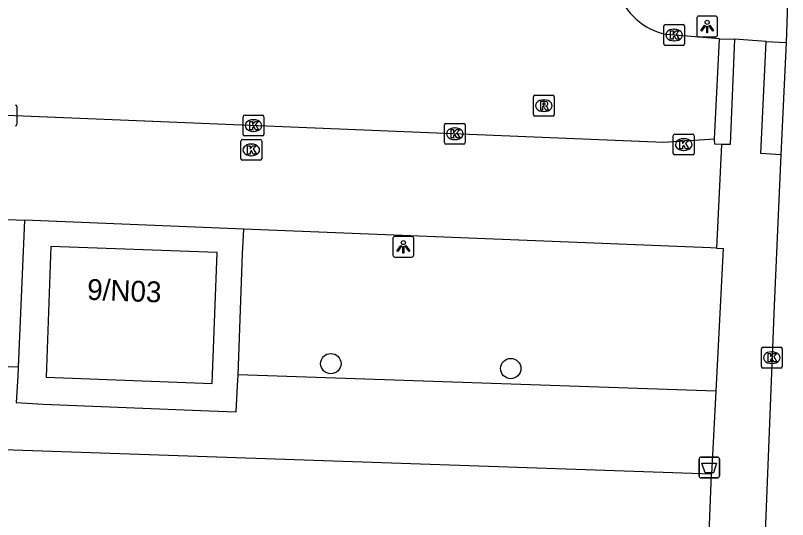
# Model space of a CAD drawing. Extents: x 160787 to 161428, y 386828 to 387483.
# Drawn here: x 160898.21 to 160935.33, y 387331.38 to 387355.63 of the extents above; entities that cross this region are included whole.
import ezdxf

# ---------------------------------------------------------------- set-up
doc = ezdxf.new("R2010")
doc.units = 0
for name, color, linetype in [('IMGEO_Afvalbak', 7, 'Continuous'), ('IMGEO_Boom', 7, 'Continuous'), ('IMGEO_Groenvoorziening', 7, 'Continuous'), ('IMGEO_Kolk', 7, 'Continuous'), ('IMGEO_Lichtpunt', 7, 'Continuous'), ('IMGEO_Pand', 7, 'Continuous'), ('IMGEO_Pand_nummerreeks', 7, 'Continuous'), ('IMGEO_Parkeervlak_open', 7, 'Continuous'), ('IMGEO_Rijbaan_lokaal_gesloten', 7, 'Continuous'), ('IMGEO_Rijbaan_lokaal_open', 7, 'Continuous'), ('IMGEO_Rioolput', 7, 'Continuous'), ('IMGEO_Voetpad_open', 7, 'Continuous')]:
    doc.layers.add(name, color=color, linetype=linetype)

msp = doc.modelspace()

# ---------------------------------------------------------------- linework, layer by layer
at = {"layer": 'IMGEO_Afvalbak'}
for p, q in [((160931.074, 387333.485), (160931.074, 387334.285)), ((160931.074, 387334.285), (160931.074, 387333.485)), ((160931.174, 387334.385), (160931.964, 387334.385)), ((160931.964, 387334.385), (160931.174, 387334.385)), ((160932.064, 387334.285), (160932.064, 387333.485)), ((160932.064, 387333.485), (160932.064, 387334.285)), ((160931.964, 387333.385), (160931.174, 387333.385)), ((160931.174, 387333.385), (160931.964, 387333.385))]:
    msp.add_line(p, q, dxfattribs=at)
msp.add_lwpolyline([(160931.217, 387334.099), (160931.921, 387334.099), (160931.772, 387333.629), (160931.366, 387333.629), (160931.217, 387334.099)], dxfattribs=at)
for centre, start, end in [((160931.174, 387334.285), 90, 180), ((160931.174, 387334.285), 90, 180), ((160931.964, 387334.285), 0, 90), ((160931.964, 387334.285), 360, 90), ((160931.174, 387333.485), 180, 270), ((160931.174, 387333.485), 180, 270), ((160931.964, 387333.485), 270, 0), ((160931.964, 387333.485), 270, 0)]:
    msp.add_arc(centre, 0.1, start, end, dxfattribs=at)
at = {"layer": 'IMGEO_Boom'}
for centre in [(160913.371, 387338.88), (160922.02, 387338.643)]:
    msp.add_circle(centre, 0.489, dxfattribs=at)
at = {"layer": 'IMGEO_Groenvoorziening'}
for points in [[(160898.334, 387338.707), (160887.579, 387339.077), (160887.001, 387339.073)], [(160931.88, 387337.553), (160908.908, 387338.343)], [(160931.673, 387333.557), (160897.152, 387334.745)]]:
    msp.add_lwpolyline(points, dxfattribs=at)
at = {"layer": 'IMGEO_Kolk'}
for p, q in [((160929.381, 387354.258), (160929.381, 387355.11)), ((160929.456, 387355.184), (160930.308, 387355.184)), ((160929.869, 387354.964), (160929.894, 387354.964)), ((160930.382, 387355.11), (160930.382, 387354.258)), ((160930.308, 387354.184), (160929.456, 387354.184)), ((160929.892, 387354.404), (160929.867, 387354.404)), ((160898.28, 387351.243), (160898.28, 387350.391)), ((160909.155, 387349.905), (160909.155, 387350.757)), ((160909.23, 387350.831), (160910.082, 387350.831)), ((160909.643, 387350.611), (160909.668, 387350.611)), ((160910.156, 387350.757), (160910.156, 387349.905)), ((160918.833, 387349.509), (160918.833, 387350.361)), ((160918.908, 387350.435), (160919.76, 387350.435)), ((160919.321, 387350.215), (160919.346, 387350.215)), ((160919.834, 387350.361), (160919.834, 387349.509)), ((160910.082, 387349.831), (160909.23, 387349.831)), ((160909.666, 387350.051), (160909.641, 387350.051)), ((160929.839, 387348.991), (160929.839, 387349.843)), ((160929.914, 387349.917), (160930.766, 387349.917)), ((160930.84, 387349.843), (160930.84, 387348.991)), ((160909.046, 387348.733), (160909.046, 387349.585)), ((160909.121, 387349.659), (160909.973, 387349.659)), ((160909.534, 387349.439), (160909.559, 387349.439)), ((160910.047, 387349.585), (160910.047, 387348.733)), ((160919.76, 387349.435), (160918.908, 387349.435)), ((160919.344, 387349.655), (160919.319, 387349.655)), ((160930.327, 387349.697), (160930.352, 387349.697)), ((160930.35, 387349.137), (160930.325, 387349.137)), ((160909.973, 387348.659), (160909.121, 387348.659)), ((160909.557, 387348.879), (160909.532, 387348.879)), ((160930.766, 387348.917), (160929.914, 387348.917)), ((160934.075, 387338.74), (160934.075, 387339.592)), ((160934.15, 387339.666), (160935.002, 387339.666)), ((160934.563, 387339.446), (160934.588, 387339.446)), ((160935.076, 387339.592), (160935.076, 387338.74)), ((160935.002, 387338.666), (160934.15, 387338.666)), ((160934.586, 387338.886), (160934.561, 387338.886))]:
    msp.add_line(p, q, dxfattribs=at)
for points in [[(160929.381, 387354.258), (160929.381, 387355.11)], [(160929.456, 387355.184), (160930.308, 387355.184)], [(160930.382, 387355.11), (160930.382, 387354.258)], [(160929.702, 387354.884), (160929.825, 387354.884), (160929.825, 387354.733), (160929.955, 387354.884), (160930.119, 387354.884), (160929.973, 387354.733), (160930.126, 387354.484), (160929.974, 387354.484), (160929.889, 387354.648), (160929.825, 387354.581), (160929.825, 387354.484), (160929.702, 387354.484), (160929.702, 387354.884)], [(160930.308, 387354.184), (160929.456, 387354.184)], [(160898.28, 387351.243), (160898.28, 387350.391)], [(160909.155, 387349.905), (160909.155, 387350.757)], [(160909.23, 387350.831), (160910.082, 387350.831)], [(160909.476, 387350.531), (160909.599, 387350.531), (160909.599, 387350.38), (160909.729, 387350.531), (160909.893, 387350.531), (160909.747, 387350.38), (160909.9, 387350.131), (160909.748, 387350.131), (160909.663, 387350.295), (160909.599, 387350.228), (160909.599, 387350.131), (160909.476, 387350.131), (160909.476, 387350.531)], [(160910.156, 387350.757), (160910.156, 387349.905)], [(160918.833, 387349.509), (160918.833, 387350.361)], [(160918.908, 387350.435), (160919.76, 387350.435)], [(160919.154, 387350.135), (160919.277, 387350.135), (160919.277, 387349.984), (160919.407, 387350.135), (160919.571, 387350.135), (160919.425, 387349.984), (160919.578, 387349.735), (160919.426, 387349.735), (160919.341, 387349.899), (160919.277, 387349.832), (160919.277, 387349.735), (160919.154, 387349.735), (160919.154, 387350.135)], [(160919.834, 387350.361), (160919.834, 387349.509)], [(160910.082, 387349.831), (160909.23, 387349.831)], [(160929.839, 387348.991), (160929.839, 387349.843)], [(160929.914, 387349.917), (160930.766, 387349.917)], [(160930.84, 387349.843), (160930.84, 387348.991)], [(160909.046, 387348.733), (160909.046, 387349.585)], [(160909.121, 387349.659), (160909.973, 387349.659)], [(160909.367, 387349.359), (160909.49, 387349.359), (160909.49, 387349.208), (160909.62, 387349.359), (160909.784, 387349.359), (160909.638, 387349.208), (160909.791, 387348.959), (160909.639, 387348.959), (160909.554, 387349.123), (160909.49, 387349.056), (160909.49, 387348.959), (160909.367, 387348.959), (160909.367, 387349.359)], [(160910.047, 387349.585), (160910.047, 387348.733)], [(160919.76, 387349.435), (160918.908, 387349.435)], [(160930.16, 387349.617), (160930.283, 387349.617), (160930.283, 387349.466), (160930.413, 387349.617), (160930.577, 387349.617), (160930.431, 387349.466), (160930.584, 387349.217), (160930.432, 387349.217), (160930.347, 387349.381), (160930.283, 387349.314), (160930.283, 387349.217), (160930.16, 387349.217), (160930.16, 387349.617)], [(160909.973, 387348.659), (160909.121, 387348.659)], [(160930.766, 387348.917), (160929.914, 387348.917)], [(160934.075, 387338.74), (160934.075, 387339.592)], [(160934.15, 387339.666), (160935.002, 387339.666)], [(160934.396, 387339.366), (160934.519, 387339.366), (160934.519, 387339.215), (160934.649, 387339.366), (160934.813, 387339.366), (160934.667, 387339.215), (160934.82, 387338.966), (160934.668, 387338.966), (160934.583, 387339.13), (160934.519, 387339.063), (160934.519, 387338.966), (160934.396, 387338.966), (160934.396, 387339.366)], [(160935.076, 387339.592), (160935.076, 387338.74)], [(160935.002, 387338.666), (160934.15, 387338.666)]]:
    msp.add_lwpolyline(points, dxfattribs=at)
for centre, start, end in [((160929.458, 387355.108), 91.552, 178.448), ((160929.458, 387355.108), 91.552, 178.448), ((160930.306, 387355.108), 1.552, 88.448), ((160930.306, 387355.108), 1.552, 88.448), ((160929.458, 387354.26), 181.552, 268.448), ((160929.458, 387354.26), 181.552, 268.448), ((160930.306, 387354.26), 271.552, 358.448), ((160930.306, 387354.26), 271.552, 358.448), ((160898.204, 387351.241), 1.552, 88.448), ((160898.204, 387351.241), 1.552, 88.448), ((160909.232, 387350.755), 91.552, 178.448), ((160909.232, 387350.755), 91.552, 178.448), ((160910.08, 387350.755), 1.552, 88.448), ((160910.08, 387350.755), 1.552, 88.448), ((160898.204, 387350.393), 271.552, 358.448), ((160898.204, 387350.393), 271.552, 358.448), ((160918.91, 387350.359), 91.552, 178.448), ((160918.91, 387350.359), 91.552, 178.448), ((160919.758, 387350.359), 1.552, 88.448), ((160919.758, 387350.359), 1.552, 88.448), ((160909.232, 387349.907), 181.552, 268.448), ((160909.232, 387349.907), 181.552, 268.448), ((160910.08, 387349.907), 271.552, 358.448), ((160910.08, 387349.907), 271.552, 358.448), ((160929.916, 387349.841), 91.552, 178.448), ((160929.916, 387349.841), 91.552, 178.448), ((160930.764, 387349.841), 1.552, 88.448), ((160930.764, 387349.841), 1.552, 88.448), ((160909.123, 387349.583), 91.552, 178.448), ((160909.123, 387349.583), 91.552, 178.448), ((160909.971, 387349.583), 1.552, 88.448), ((160909.971, 387349.583), 1.552, 88.448), ((160918.91, 387349.511), 181.552, 268.448), ((160918.91, 387349.511), 181.552, 268.448), ((160919.758, 387349.511), 271.552, 358.448), ((160919.758, 387349.511), 271.552, 358.448), ((160929.916, 387348.993), 181.552, 268.448), ((160929.916, 387348.993), 181.552, 268.448), ((160930.764, 387348.993), 271.552, 358.448), ((160930.764, 387348.993), 271.552, 358.448), ((160909.123, 387348.735), 181.552, 268.448), ((160909.123, 387348.735), 181.552, 268.448), ((160909.971, 387348.735), 271.552, 358.448), ((160909.971, 387348.735), 271.552, 358.448), ((160934.152, 387339.59), 91.552, 178.448), ((160934.152, 387339.59), 91.552, 178.448), ((160935, 387339.59), 1.552, 88.448), ((160935, 387339.59), 1.552, 88.448), ((160934.152, 387338.742), 181.552, 268.448), ((160934.152, 387338.742), 181.552, 268.448), ((160935, 387338.742), 271.552, 358.448), ((160935, 387338.742), 271.552, 358.448)]:
    msp.add_arc(centre, 0.0765, start, end, dxfattribs=at)
for centre, major_axis, ratio, start_param, end_param in [((160929.868, 387354.684), (-0.387, 0.002), 0.722429, 4.712389, 7.853982), ((160929.893, 387354.684), (-0.39, 0.002), 0.717154, 1.570796, 4.712389), ((160909.642, 387350.331), (-0.387, 0.002), 0.722429, 4.712389, 7.853982), ((160909.667, 387350.331), (-0.39, 0.002), 0.717154, 1.570796, 4.712389), ((160919.32, 387349.935), (-0.387, 0.002), 0.722429, 4.712389, 7.853982), ((160919.345, 387349.935), (-0.39, 0.002), 0.717154, 1.570796, 4.712389), ((160909.533, 387349.159), (-0.387, 0.002), 0.722429, 4.712389, 7.853982), ((160909.558, 387349.159), (-0.39, 0.002), 0.717154, 1.570796, 4.712389), ((160930.326, 387349.417), (-0.387, 0.002), 0.722429, 4.712389, 7.853982), ((160930.351, 387349.417), (-0.39, 0.002), 0.717154, 1.570796, 4.712389), ((160934.562, 387339.166), (-0.387, 0.002), 0.722429, 4.712389, 7.853982), ((160934.587, 387339.166), (-0.39, 0.002), 0.717154, 1.570796, 4.712389)]:
    msp.add_ellipse(centre, major_axis=major_axis, ratio=ratio, start_param=start_param, end_param=end_param, dxfattribs=at)
at = {"layer": 'IMGEO_Lichtpunt'}
for p, q in [((160930.967, 387355.497), (160930.967, 387354.69)), ((160930.967, 387355.497), (160930.967, 387354.69)), ((160931.869, 387355.592), (160931.061, 387355.592)), ((160931.869, 387355.592), (160931.061, 387355.592)), ((160931.963, 387354.69), (160931.963, 387355.497)), ((160931.963, 387354.69), (160931.963, 387355.497)), ((160931.061, 387354.596), (160931.869, 387354.596)), ((160931.061, 387354.596), (160931.869, 387354.596)), ((160916.36, 387344.903), (160916.36, 387344.096)), ((160916.36, 387344.903), (160916.36, 387344.096)), ((160917.262, 387344.998), (160916.454, 387344.998)), ((160917.262, 387344.998), (160916.454, 387344.998)), ((160917.356, 387344.096), (160917.356, 387344.903)), ((160917.356, 387344.096), (160917.356, 387344.903)), ((160916.454, 387344.002), (160917.262, 387344.002)), ((160916.454, 387344.002), (160917.262, 387344.002))]:
    msp.add_line(p, q, dxfattribs=at)
for points in [[(160931.341, 387355.161), (160931.38, 387355.133), (160931.192, 387354.871), (160931.154, 387354.898), (160931.341, 387355.161)], [(160931.443, 387355.113), (160931.49, 387355.113), (160931.49, 387354.791), (160931.443, 387354.791), (160931.443, 387355.113)], [(160931.553, 387355.133), (160931.591, 387355.16), (160931.778, 387354.898), (160931.739, 387354.87), (160931.553, 387355.133)], [(160916.734, 387344.567), (160916.773, 387344.539), (160916.585, 387344.277), (160916.547, 387344.304), (160916.734, 387344.567)], [(160916.946, 387344.539), (160916.984, 387344.566), (160917.171, 387344.304), (160917.132, 387344.276), (160916.946, 387344.539)], [(160916.836, 387344.519), (160916.883, 387344.519), (160916.883, 387344.197), (160916.836, 387344.197), (160916.836, 387344.519)]]:
    msp.add_lwpolyline(points, dxfattribs=at)
for centre in [(160931.466, 387355.295), (160916.859, 387344.701)]:
    msp.add_circle(centre, 0.0994, dxfattribs=at)
for centre, start, end in [((160931.061, 387355.497), 90, 180), ((160931.061, 387355.497), 90, 180), ((160931.869, 387355.497), 0, 90), ((160931.869, 387355.497), 0, 90), ((160931.061, 387354.69), 180, 270), ((160931.061, 387354.69), 180, 270), ((160931.869, 387354.69), 270, 0), ((160931.869, 387354.69), 270, 360), ((160916.454, 387344.903), 90, 180), ((160916.454, 387344.903), 90, 180), ((160917.262, 387344.903), 0, 90), ((160917.262, 387344.903), 0, 90), ((160916.454, 387344.096), 180, 270), ((160916.454, 387344.096), 180, 270), ((160917.262, 387344.096), 270, 0), ((160917.262, 387344.096), 270, 360)]:
    msp.add_arc(centre, 0.0946, start, end, dxfattribs=at)
at = {"layer": 'IMGEO_Pand'}
msp.add_lwpolyline([(160907.907, 387344.221), (160899.912, 387344.52), (160899.676, 387338.225), (160907.671, 387337.925), (160907.907, 387344.221)], dxfattribs=at)
at = {"layer": 'IMGEO_Parkeervlak_open'}
for points in [[(160886.924, 387346.248), (160887.833, 387346.211), (160898.638, 387345.777)], [(160931.908, 387344.432), (160931.62, 387344.451), (160909.185, 387345.353)]]:
    msp.add_lwpolyline(points, dxfattribs=at)
at = {"layer": 'IMGEO_Rijbaan_lokaal_gesloten'}
for points in [[(160935.332, 387356.239), (160935.259, 387354.331)], [(160935.259, 387354.331), (160935.003, 387348.923)], [(160935.003, 387348.923), (160934.696, 387341.673), (160933.149, 387302.881), (160933.124, 387302.25), (160933.019, 387301.591), (160932.815, 387298.644)]]:
    msp.add_lwpolyline(points, dxfattribs=at)
at = {"layer": 'IMGEO_Rijbaan_lokaal_open'}
for points in [[(160932.055, 387354.496), (160929.521, 387354.715)], [(160931.826, 387349.668), (160932.055, 387354.496)], [(160931.826, 387349.668), (160929.389, 387349.523), (160881.402, 387351.487)]]:
    msp.add_lwpolyline(points, dxfattribs=at)
msp.add_arc((160930.121, 387357.752), 3.096, 197.3147, 258.8292, dxfattribs=at)
at = {"layer": 'IMGEO_Rioolput'}
for p, q in [((160923.111, 387350.861), (160923.111, 387351.713)), ((160923.186, 387351.787), (160924.038, 387351.787)), ((160924.112, 387351.713), (160924.112, 387350.861)), ((160923.599, 387351.567), (160923.624, 387351.567)), ((160923.622, 387351.007), (160923.597, 387351.007)), ((160924.038, 387350.787), (160923.186, 387350.787))]:
    msp.add_line(p, q, dxfattribs=at)
for points in [[(160923.111, 387350.861), (160923.111, 387351.713)], [(160923.186, 387351.787), (160924.038, 387351.787)], [(160924.112, 387351.713), (160924.112, 387350.861)], [(160923.7, 387351.485), (160923.448, 387351.487), (160923.448, 387351.087)], [(160923.448, 387351.087), (160923.572, 387351.087), (160923.572, 387351.249), (160923.583, 387351.249)], [(160923.626, 387351.406), (160923.572, 387351.406), (160923.572, 387351.325)], [(160923.572, 387351.325), (160923.624, 387351.325)], [(160923.63, 387351.22), (160923.701, 387351.087), (160923.841, 387351.087), (160923.776, 387351.213)], [(160924.038, 387350.787), (160923.186, 387350.787)]]:
    msp.add_lwpolyline(points, dxfattribs=at)
for centre, radius, start, end in [((160923.188, 387351.711), 0.0765, 91.552, 178.448), ((160923.188, 387351.711), 0.0765, 91.552, 178.448), ((160924.036, 387351.711), 0.0765, 1.552, 88.448), ((160924.036, 387351.711), 0.0765, 1.552, 88.448), ((160923.582, 387351.196), 0.0533, 26.0293, 88.6989), ((160923.608, 387351.514), 0.19, 274.7715, 282.9687), ((160923.632, 387351.31), 0.0964, 77.0061, 93.1865), ((160923.646, 387351.367), 0.0378, 276.6634, 79.6772), ((160923.699, 387351.375), 0.109, 350.3612, 89.416), ((160923.697, 387351.375), 0.112, 277.5842, 350.9817), ((160923.681, 387351.16), 0.108, 29.5134, 73.7905), ((160923.188, 387350.863), 0.0765, 181.552, 268.448), ((160923.188, 387350.863), 0.0765, 181.552, 268.448), ((160924.036, 387350.863), 0.0765, 271.552, 358.448), ((160924.036, 387350.863), 0.0765, 271.552, 358.448)]:
    msp.add_arc(centre, radius, start, end, dxfattribs=at)
for centre, major_axis, ratio, start_param, end_param in [((160923.598, 387351.287), (-0.387, 0.002), 0.722429, 4.712389, 7.853982), ((160923.623, 387351.287), (-0.39, 0.002), 0.717154, 1.570796, 4.712389)]:
    msp.add_ellipse(centre, major_axis=major_axis, ratio=ratio, start_param=start_param, end_param=end_param, dxfattribs=at)
at = {"layer": 'IMGEO_Voetpad_open'}
for points in [[(160932.055, 387354.496), (160932.775, 387354.483)], [(160932.775, 387354.483), (160932.572, 387349.418), (160932.152, 387349.412)], [(160934.308, 387354.373), (160932.775, 387354.483)], [(160935.003, 387348.923), (160934.05, 387348.981), (160934.308, 387354.373)], [(160934.308, 387354.373), (160935.259, 387354.331)], [(160932.152, 387349.412), (160931.841, 387349.435), (160931.826, 387349.668)], [(160932.152, 387349.412), (160931.908, 387344.432)], [(160898.638, 387345.777), (160898.334, 387338.707)], [(160909.185, 387345.353), (160898.638, 387345.777)], [(160908.908, 387338.343), (160909.124, 387344.16), (160909.185, 387345.353)], [(160931.908, 387344.432), (160932.232, 387344.411), (160931.88, 387337.553)], [(160898.334, 387338.707), (160898.315, 387338.276), (160898.243, 387337.012), (160899.544, 387336.937), (160907.527, 387336.61), (160908.815, 387336.569), (160908.888, 387337.808), (160908.908, 387338.343)], [(160931.88, 387337.553), (160931.737, 387334.779), (160931.673, 387333.557)], [(160929.448, 387298.803), (160929.609, 387298.921), (160929.758, 387299.053), (160929.895, 387299.198), (160930.019, 387299.354), (160930.128, 387299.521), (160930.221, 387299.697), (160930.299, 387299.881), (160930.36, 387300.07), (160930.368, 387300.102), (160930.559, 387305.234), (160931.537, 387329.895), (160931.673, 387333.557)]]:
    msp.add_lwpolyline(points, dxfattribs=at)

# ---------------------------------------------------------------- texts
at = {"layer": 'IMGEO_Pand_nummerreeks'}
msp.add_text('9/N03', height=1, rotation=357.8571, dxfattribs=at).set_placement((160901.641, 387341.954))

doc.saveas('drawing.dxf')
